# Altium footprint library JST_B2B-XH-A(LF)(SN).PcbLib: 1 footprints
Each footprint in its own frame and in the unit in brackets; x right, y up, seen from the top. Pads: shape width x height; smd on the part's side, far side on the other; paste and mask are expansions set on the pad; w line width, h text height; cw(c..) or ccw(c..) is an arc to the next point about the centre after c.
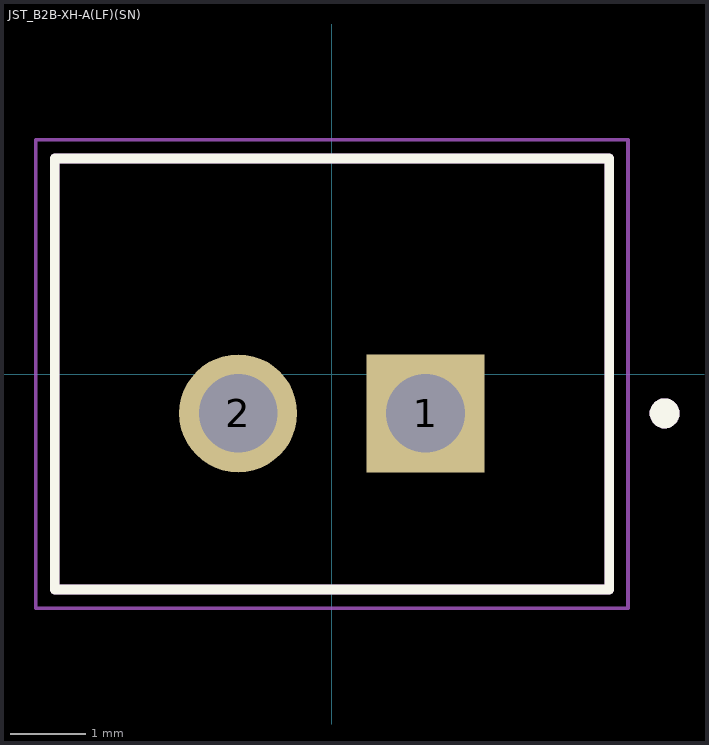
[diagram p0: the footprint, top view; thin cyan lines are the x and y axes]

## JST_B2B-XH-A(LF)(SN) [mm]
height 7
pads (2):
  rect 1.575x1.575 / inner round 1.575 / far side rect 1.575x1.575 hole 1.05: 1(1.25,-0.525)
  round 1.575 hole 1.05: 2(-1.25,-0.525)
Top Overlay:
  circle w0.2: c4.44,-0.525 r0.1
  lines w0.127: -3.7,-2.875 3.7,-2.875 3.7,2.875 -3.7,2.875 -3.7,-2.875
Assembly Top:
  circle w0.2: c4.44,-0.525 r0.1
  lines w0.127: -3.7,-2.875 3.7,-2.875 3.7,2.875 -3.7,2.875 -3.7,-2.875
Courtyard Top:
  lines w0.05: -3.95,-3.125 -3.95,3.125 3.95,3.125 3.95,-3.125 -3.95,-3.125
3D body "step_temp.STEP": height 7, standoff -3.4, extent -3.7,-2.875 3.7,2.875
